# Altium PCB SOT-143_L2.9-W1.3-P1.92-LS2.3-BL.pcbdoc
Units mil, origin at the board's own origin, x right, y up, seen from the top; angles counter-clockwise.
Board outline 631.94 x 622.04 mil, 2 copper layers (Top Layer, Bottom Layer), stack 0 mil thick; 1 components, 0 nets, 4 pads, 0 vias.
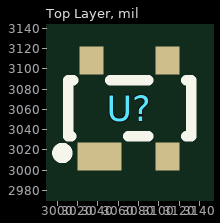
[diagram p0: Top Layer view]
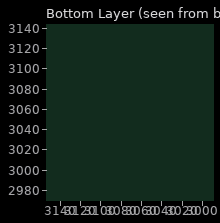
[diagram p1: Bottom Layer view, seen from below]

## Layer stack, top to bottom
Top Layer: signal copper (thickness not stored)
Bottom Layer: signal copper (thickness not stored)

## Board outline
3381.94,2750 2750,2750 2750,3372.04 3381.94,3372.04

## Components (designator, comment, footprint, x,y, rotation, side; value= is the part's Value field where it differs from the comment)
U? "" SOT-143_L2.9-W1.3-P1.92-LS2.3-BL 3071,3061.02 r0 top

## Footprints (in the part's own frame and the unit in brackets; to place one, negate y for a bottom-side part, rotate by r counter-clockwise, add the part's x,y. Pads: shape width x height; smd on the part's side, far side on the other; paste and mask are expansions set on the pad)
SOT-143_L2.9-W1.3-P1.92-LS2.3-BL [mm]
  rect 1.1x0.7 smd paste+0 mask+0.05: 1(-0.75,-1.2)
  rect 0.6x0.7 smd paste+0 mask+0.05: 2(0.95,-1.2) 3(0.95,1.2) 4(-0.95,1.2)
  silkscreen extent -1.8,-1.24 1.55,0.7

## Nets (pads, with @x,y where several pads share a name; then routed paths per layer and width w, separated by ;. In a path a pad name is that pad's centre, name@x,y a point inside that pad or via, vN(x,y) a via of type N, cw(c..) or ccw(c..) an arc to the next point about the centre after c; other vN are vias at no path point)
pads on no net: U?.1 U?.2 U?.3 U?.4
